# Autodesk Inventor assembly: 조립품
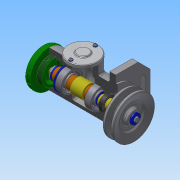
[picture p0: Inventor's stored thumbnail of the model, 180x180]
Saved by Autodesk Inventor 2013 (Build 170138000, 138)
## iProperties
Created: 2017-10
Part Number: 조립품
Document SubType Name: Assembly
Designer: Windows7
Author: Windows7
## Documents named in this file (20)
- C:\Users\Windows7\Desktop\471008V1008\조립품.iam
- C:\Users\Windows7\Desktop\471008V1008\본체.ipt
- C:\Users\Windows7\Desktop\471008V1008\축.ipt
- C:\Users\Windows7\Desktop\471008V1008\부시1.ipt
- C:\Users\Windows7\Desktop\471008V1008\베어링 15 x 35 x 11.ipt
- C:\Users\Windows7\Desktop\471008V1008\멈춤링 35x1.6.ipt
- C:\Users\Windows7\Desktop\471008V1008\부시2.ipt
- C:\Users\Windows7\Desktop\471008V1008\와셔 10x21.ipt
- C:\Users\Windows7\Desktop\471008V1008\너트 M10.ipt
- C:\Users\Windows7\Desktop\471008V1008\멈춤링 15 x 1.ipt
- C:\Users\Windows7\Desktop\471008V1008\오일 실 15 25 7.ipt
- C:\Users\Windows7\Desktop\471008V1008\키 4 x 4 x 18.ipt
- C:\Users\Windows7\Desktop\471008V1008\V-벨트풀리.ipt
- C:\Users\Windows7\Desktop\471008V1008\와셔 4x16.ipt
- C:\Users\Windows7\Desktop\471008V1008\볼트 M4 x 10.ipt
- C:\Users\Windows7\Desktop\471008V1008\사이드 커버.ipt
- 사이드 커버.ipt
- C:\Users\Windows7\Desktop\471008V1008\탑 커버.ipt
- C:\Users\Windows7\Desktop\471008V1008\와셔 3x6.ipt
- C:\Users\Windows7\Desktop\471008V1008\십자볼트 M3 x 10.ipt
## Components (2 placed, 2 different names)
1. V-벨트풀리:1 — 각도:1
2. ISO 4017 M4 x 10:1
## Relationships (1: Angle 1)
- 각도:1 [Angle]: V-벨트풀리:1
